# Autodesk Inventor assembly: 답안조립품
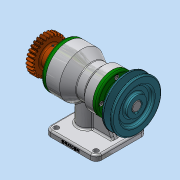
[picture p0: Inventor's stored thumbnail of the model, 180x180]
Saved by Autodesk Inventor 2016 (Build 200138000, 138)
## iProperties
Created: 2019-01
Part Number: 답안조립품
Material: 일반
Document SubType Name: Assembly
Designer: Administrator
Author: Administrator
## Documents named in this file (15)
- C:\Users\Administrator\Desktop\490107V1002\답안조립품.iam
- C:\Users\Administrator\Desktop\490107V1002\1-본체.ipt
- C:\Users\Administrator\Desktop\490107V1002\4-축.ipt
- C:\Users\Administrator\Desktop\490107V1002\2-베어링 6203.ipt
- C:\Users\Administrator\Desktop\490107V1002\3-베어링 6205.ipt
- C:\Users\Administrator\Desktop\490107V1002\5-앞커버.ipt
- C:\Users\Administrator\Desktop\490107V1002\7-오일 실 25 38 8.ipt
- C:\Users\Administrator\Desktop\490107V1002\6-뒤커버.ipt
- C:\Users\Administrator\Desktop\490107V1002\8-오일 실 17 30 8.ipt
- C:\Users\Administrator\Desktop\490107V1002\10-키 6 x 6 x 18.ipt
- C:\Users\Administrator\Desktop\490107V1002\12-스퍼기어.ipt
- C:\Users\Administrator\Desktop\490107V1002\14-멈춤나사 M3.ipt
- C:\Users\Administrator\Desktop\490107V1002\11-키 5 x 5 x 20.ipt
- C:\Users\Administrator\Desktop\490107V1002\13-V-벨트풀리.ipt
- C:\Users\Administrator\Desktop\490107V1002\9-볼트 M4.ipt
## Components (14 placed, 13 different names)
1. 1-본체:1
2. 4-축:1 — 플러쉬:1, 플러쉬:2
3. 2-베어링 6203:1
4. 3-베어링 6205:1
5. 5-앞커버:1
6. 7-오일 실 25 38 8:1
7. 6-뒤커버:1
8. 8-오일 실 17 30 8:1
9. 10-키 6 x 6 x 18:1 — 각도:1
10. 12-스퍼기어:1 — 각도:1, 플러쉬:1
11. 14-멈춤나사 M3:1
12. 11-키 5 x 5 x 20:1
13. 13-V-벨트풀리:1 — 플러쉬:2
14. 14-멈춤나사 M3:2
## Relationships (3: Flush 2, Angle 1)
- 각도:1 [Angle]: 10-키 6 x 6 x 18:1 ↔ 12-스퍼기어:1
- 플러쉬:1 [Flush]: 4-축:1 ↔ 12-스퍼기어:1
- 플러쉬:2 [Flush]: 4-축:1 ↔ 13-V-벨트풀리:1
